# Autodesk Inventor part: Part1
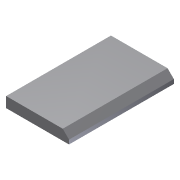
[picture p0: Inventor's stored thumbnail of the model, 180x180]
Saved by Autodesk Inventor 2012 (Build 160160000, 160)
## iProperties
Shininess: 64.0
Length Units: 11269
Angle Units: 11279
Time Units: 11290
Mass Units: 11283
Length Display Precision: 3
Angle Display Precision: 2
Compacted: True
Part Number: Part1
Document SubType Name: Modeling
Created: 2003-01
Designer: Owner
Density: 1 g/cm^3
Material: Default
Density: 0.0
Volumn: 0.0
Area: 0.0
PropertySet Name: Model Information
Control State: 0
Master: False
Checked Out: False
Author: Owner
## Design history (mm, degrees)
sketch "Sketch1"
  geometry: L1 (-18.987, 24.241)-(11.013, 24.241); L2 (11.013, 24.241)-(11.013, -25.759); L3 (11.013, -25.759)-(-18.987, -25.759); L4 (-18.987, -25.759)-(-18.987, 24.241)
  constraints: 8 end point, 2 parallel, 1 horizontal, 1 perpendicular
  dimensions: "d0" = 30 distance of L1.start L1.end; "d1" = 50 distance of L3.end L1.start
extrude "Extrusion1" new body sketch "Sketch1" distance "d2" = 5; taper "d3" = 0 deg
chamfer "Chamfer1" distance "d4" = 3; stored, may be unused: second distance "d5" = 2, angle "d6" = 45 deg
body "Solid1"
